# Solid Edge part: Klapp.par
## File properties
Author: Türk
Template: Iso Part.par
Last saved by: Türk
Revision: 14
Application: Solid Edge
Accuracy: 0,990
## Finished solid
Body 1: solid body, 6 faces, 5 edges, 0 vertices.
  Faces by surface: cylinder 2, plane 2, torus 2
  Edges by curve: circle 5
Bounding box of the edges (mm; curved faces can reach further): 22.000 x 73.000 x 22.000, from (-11, -71, -11) to (11, 2, 11).
Cylindrical faces by radius (mm): R3 x1, R11 x1
Toroidal faces (ring radius, tube radius in mm): R1.9 r1.1 x1, R14 r11 x1
Planar faces by outward normal: +y 1, -y 1
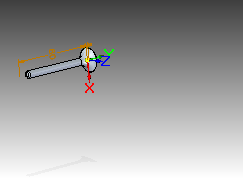
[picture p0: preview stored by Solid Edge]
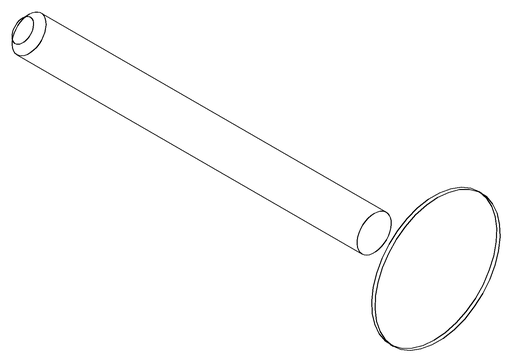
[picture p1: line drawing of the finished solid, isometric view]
